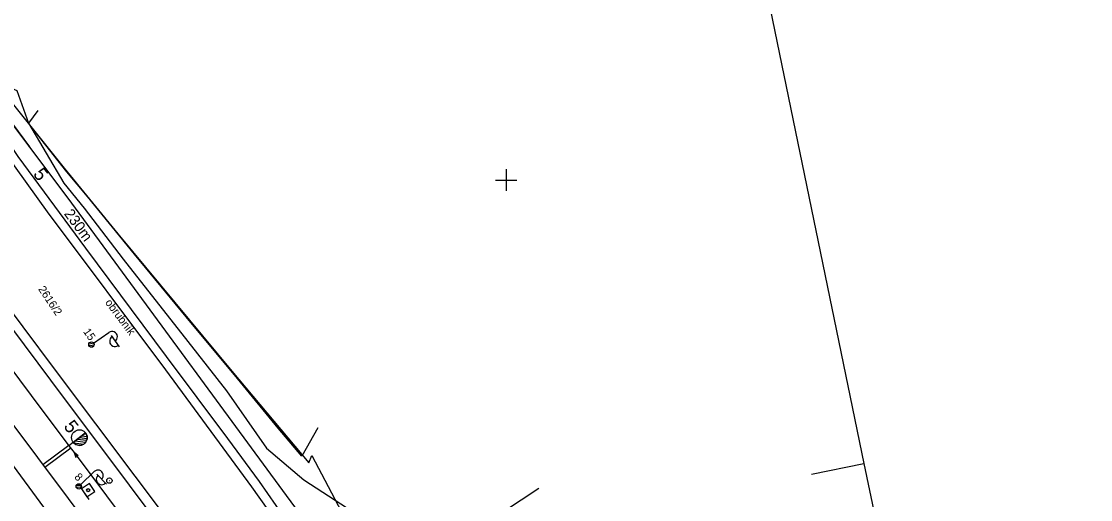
# Model space of a CAD drawing. Extents: x -804166 to -803706, y -1151030 to -1150147.
# Drawn here: x -803990.8 to -803790.5, y -1150359.8 to -1150270.3 of the extents above; entities that cross this region are included whole.
import ezdxf

# ---------------------------------------------------------------- set-up
doc = ezdxf.new("R2010")
doc.units = 0
for name, color, linetype in [('0381KM032-037P - Vrstva 1', 7, 'Continuous'), ('0381KM032-037P - Vrstva 17', 7, 'Continuous'), ('0381KM032-037P - Vrstva 2', 7, 'Continuous'), ('0381KM032-037P - Vrstva 25', 7, 'Continuous'), ('0381KM032-037P - Vrstva 27', 7, 'Continuous'), ('0381KM032-037P - Vrstva 3', 7, 'Continuous'), ('0381KM032-037P - Vrstva 4', 7, 'Continuous'), ('0381KM032-037P - Vrstva 49', 7, 'Continuous'), ('0381KM032-037P - Vrstva 51', 7, 'Continuous'), ('0381KM032-037P - Vrstva 57', 7, 'Continuous'), ('0381KM032-037P - Vrstva 7', 7, 'Continuous'), ('formát', 7, 'Continuous'), ('hran DP - hran DP', 7, 'Continuous'), ('krizky_1000 - Vrstva 1', 7, 'Continuous')]:
    doc.layers.add(name, color=color, linetype=linetype)

msp = doc.modelspace()

# ---------------------------------------------------------------- linework, layer by layer
at = {"layer": '0381KM032-037P - Vrstva 1'}
for points in [[(-804087.93, -1150205.28), (-804078.71, -1150215.28), (-804072.37, -1150222.52), (-804072.08, -1150222.85), (-804071.47, -1150223.58), (-804065.48, -1150230.82), (-804059.47, -1150238.51), (-804055.55, -1150243.68), (-804054.36, -1150245.27), (-804043.89, -1150259.22), (-804035.37, -1150270.61), (-804034.4, -1150271.93), (-804017.97, -1150293.92), (-804002.6, -1150314.46), (-803985.38, -1150337.43), (-803955.87, -1150376.72)], [(-804089.35, -1150206.44), (-804078.67, -1150220.7), (-804069.15, -1150233.38), (-804067.86, -1150235.11), (-804059.28, -1150246.53), (-804058.07, -1150248.16), (-804048.7, -1150260.65), (-804037.85, -1150275.13), (-804021.63, -1150296.76), (-804006.14, -1150317.34), (-803988.98, -1150340.29), (-803981.9, -1150349.73)], [(-804090.39, -1150214.38), (-804086.65, -1150219.55), (-804073.82, -1150237.11), (-804072.56, -1150238.83), (-804064.05, -1150250.31), (-804062.81, -1150251.97), (-804052.29, -1150266.05), (-804042.5, -1150279.11), (-804026.55, -1150300.33), (-804011.27, -1150320.63), (-803993.37, -1150344.49), (-803965.17, -1150382.07), (-803953.84, -1150397.19)], [(-804093.97, -1150217.42), (-804088.17, -1150225.67), (-804077.51, -1150240.28), (-804068.52, -1150252.21), (-804067.31, -1150253.81), (-804055.01, -1150270.12), (-804046.09, -1150281.93), (-804030.05, -1150303.21), (-804014.76, -1150323.52), (-803996.92, -1150347.35), (-803968.88, -1150385.42), (-803942.6, -1150419.03)], [(-804011.14, -1150262.39), (-804005.45, -1150273.41), (-803998.73, -1150284.85), (-803991.51, -1150295.63), (-803978.8, -1150312.77), (-803963.69, -1150332.99), (-803952.21, -1150348.36), (-803946.3, -1150356.39), (-803941.6, -1150363.14), (-803936.71, -1150370.83), (-803932.05, -1150378.84), (-803927.78, -1150386.91), (-803924.06, -1150395.18), (-803920.62, -1150403.65), (-803918.06, -1150410.86), (-803915.07, -1150420.32), (-803912.96, -1150427.25), (-803910.49, -1150435.34), (-803907.33, -1150445.05), (-803903.67, -1150454.38), (-803897.94, -1150464.6), (-803891.97, -1150476.6)], [(-803981.9, -1150349.73), (-803980.96, -1150350.97), (-803971.94, -1150363.03), (-803962.12, -1150376.15)], [(-803981.9, -1150349.73), (-803980.96, -1150350.97), (-803971.94, -1150363.03), (-803963.66, -1150377.12)]]:
    msp.add_lwpolyline(points, dxfattribs=at)
at = {"layer": '0381KM032-037P - Vrstva 17'}
for p, q in [((-803987.75, -1150286.99), (-803989.47, -1150289.34)), ((-803935.29, -1150346.34), (-803938.3, -1150351.66))]:
    msp.add_line(p, q, dxfattribs=at)
msp.add_lwpolyline([(-803938.3, -1150351.66), (-803942.72, -1150346.43), (-803950.36, -1150337.11), (-803959.95, -1150325.57), (-803969.63, -1150313.89), (-803978.45, -1150303.11), (-803982.31, -1150298.44), (-803989.47, -1150289.34)], dxfattribs=at)
at = {"layer": '0381KM032-037P - Vrstva 2'}
for p, q in [((-803981.09, -1150349.09), (-803978.8, -1150347.27)), ((-803978.8, -1150347.27), (-803981.09, -1150349.09)), ((-803979.09, -1150347.51), (-803978.62, -1150347.56)), ((-803981.1, -1150349.09), (-803981.9, -1150349.73)), ((-803981.09, -1150349.09), (-803981.09, -1150349.09)), ((-803981.02, -1150349.17), (-803979.13, -1150349.39)), ((-803980.76, -1150348.82), (-803978.78, -1150349.06)), ((-803980.35, -1150348.49), (-803978.58, -1150348.7)), ((-803979.93, -1150348.17), (-803978.49, -1150348.33)), ((-803979.51, -1150347.84), (-803978.5, -1150347.96))]:
    msp.add_line(p, q, dxfattribs=at)
for points in [[(-803981.9, -1150349.73), (-803980.96, -1150350.97), (-803971.94, -1150363.03), (-803962.12, -1150376.15)], [(-803980.18, -1150351.59), (-803980.96, -1150350.97), (-803980.59, -1150351.9)]]:
    msp.add_lwpolyline(points, dxfattribs=at)
msp.add_circle((-803979.94, -1150348.18), 1.46, dxfattribs=at)
msp.add_arc((-803979.95, -1150348.18), 1.46, 218.2901, 38.251, dxfattribs=at)
at = {"layer": '0381KM032-037P - Vrstva 25'}
for p, q in [((-803977.29, -1150330.5), (-803974.41, -1150328.51)), ((-803974.01, -1150329.08), (-803972.53, -1150331.22)), ((-803978.2, -1150330.83), (-803977.25, -1150331.01)), ((-803978.09, -1150330.47), (-803977.23, -1150330.63)), ((-803979.7, -1150356.96), (-803977.17, -1150354.55)), ((-803976.69, -1150355.05), (-803974.89, -1150356.93)), ((-803980.55, -1150357.43), (-803979.59, -1150357.46)), ((-803980.5, -1150357.06), (-803979.62, -1150357.08))]:
    msp.add_line(p, q, dxfattribs=at)
for centre in [(-803977.7, -1150330.78), (-803977.7, -1150330.78), (-803980.07, -1150357.31), (-803980.07, -1150357.31)]:
    msp.add_circle(centre, 0.5, dxfattribs=at)
for centre, start, end in [((-803973.84, -1150329.33), 304.6353, 124.6353), ((-803973.28, -1150330.16), 123.9327, 305.3379), ((-803976.48, -1150355.27), 313.6296, 133.6296), ((-803975.8, -1150356), 132.927, 314.3322)]:
    msp.add_arc(centre, 1, start, end, dxfattribs=at)
at = {"layer": '0381KM032-037P - Vrstva 27'}
msp.add_line((-803974.39, -1150356.24), (-803974.29, -1150356.24), dxfattribs=at)
msp.add_circle((-803974.34, -1150356.24), 0.5, dxfattribs=at)
at = {"layer": '0381KM032-037P - Vrstva 3'}
for p, q in [((-803979.88, -1150357.31), (-803978.21, -1150359.75)), ((-803978.08, -1150356.8), (-803979.54, -1150357.8)), ((-803977.08, -1150358.26), (-803978.08, -1150356.8)), ((-803948.98, -1150393.6), (-803893.86, -1150357.66)), ((-803979.54, -1150357.8), (-803978.54, -1150359.26)), ((-803978.54, -1150359.26), (-803977.08, -1150358.26))]:
    msp.add_line(p, q, dxfattribs=at)
msp.add_circle((-803978.31, -1150358.03), 0.296, dxfattribs=at)
at = {"layer": '0381KM032-037P - Vrstva 4'}
for points in [[(-804015.09, -1150257.7), (-804005.61, -1150276.65), (-803997.81, -1150289.61), (-803985.99, -1150305.97), (-803963.83, -1150335.54), (-803947.69, -1150357.39), (-803941.6, -1150366.02), (-803933.49, -1150379.54), (-803925.57, -1150395.83), (-803919.57, -1150411.36), (-803915.11, -1150425.7)], [(-804033.34, -1150270.47), (-804023.51, -1150283.74), (-804006.75, -1150306.05), (-804002.75, -1150311.23), (-803984.52, -1150335.59), (-803962.04, -1150365.45)]]:
    msp.add_lwpolyline(points, dxfattribs=at)
at = {"layer": '0381KM032-037P - Vrstva 49'}
for points in [[(-804010.87, -1150255.86), (-804001.61, -1150274.67), (-803994.7, -1150286.68), (-803981.46, -1150304.36), (-803936.05, -1150366.09), (-803921.77, -1150392.54), (-803912.22, -1150419.28), (-803908.81, -1150430.91)], [(-804010.87, -1150255.86), (-804010.87, -1150255.86), (-804001.65, -1150274.6), (-803994.86, -1150286.39), (-803989.31, -1150293.81), (-803989.41, -1150293.74)], [(-803998.25, -1150280.5), (-803991.69, -1150283.27), (-803989.47, -1150289.34)], [(-803989.47, -1150289.34), (-803982.88, -1150300.61), (-803979.03, -1150305.25), (-803971.78, -1150314.79), (-803959.62, -1150330.2), (-803952.37, -1150339.47), (-803944.88, -1150350.15), (-803937.92, -1150356.12), (-803929.73, -1150361.39)]]:
    msp.add_lwpolyline(points, dxfattribs=at)
at = {"layer": '0381KM032-037P - Vrstva 51'}
msp.add_lwpolyline([(-804015.09, -1150257.7), (-804005.61, -1150276.65), (-803997.81, -1150289.61), (-803985.99, -1150305.97), (-803963.83, -1150335.54), (-803947.69, -1150357.39), (-803941.6, -1150366.02), (-803933.49, -1150379.54), (-803925.57, -1150395.83), (-803919.57, -1150411.36), (-803915.11, -1150425.7)], dxfattribs=at)
at = {"layer": '0381KM032-037P - Vrstva 7'}
for p, q in [((-803981.94, -1150349.67), (-803986.77, -1150353.29)), ((-803981.58, -1150350.15), (-803986.41, -1150353.77))]:
    msp.add_line(p, q, dxfattribs=at)
at = {"layer": 'formát'}
for p, q in [((-803875.43, -1150147.35), (-803832.97, -1150353.01)), ((-803842.77, -1150355.03), (-803832.97, -1150353.01)), ((-803842.77, -1150355.03), (-803832.97, -1150353.01)), ((-803832.97, -1150353.01), (-803790.51, -1150558.67))]:
    msp.add_line(p, q, dxfattribs=at)
at = {"layer": 'hran DP - hran DP'}
for p, q in [((-803997.02, -1150280.06), (-803982.8, -1150297.76)), ((-803982.8, -1150297.76), (-803972.77, -1150310.06)), ((-803972.77, -1150310.06), (-803951.37, -1150335.75)), ((-803951.37, -1150335.75), (-803936.98, -1150352.88)), ((-803936.98, -1150352.88), (-803936.41, -1150351.52)), ((-803936.41, -1150351.52), (-803914.94, -1150392.05))]:
    msp.add_line(p, q, dxfattribs=at)
at = {"layer": 'krizky_1000 - Vrstva 1'}
for points in [[(-803900, -1150298), (-803900, -1150302)], [(-803902, -1150300), (-803898, -1150300)]]:
    msp.add_lwpolyline(points, dxfattribs=at)

# ---------------------------------------------------------------- texts
at = {"layer": '0381KM032-037P - Vrstva 1'}
for s, height, rotation, p in [('5', 2.5, 307.3088, (-803988.73, -1150298.92)), ('230m', 2, 306.5584, (-803982.92, -1150306.33))]:
    msp.add_text(s, height=height, rotation=rotation, dxfattribs=at).set_placement(p)
at = {"layer": '0381KM032-037P - Vrstva 2'}
msp.add_text('5', height=2.5, rotation=308.2705, dxfattribs=at).set_placement((-803983.01, -1150346.15))
at = {"layer": '0381KM032-037P - Vrstva 25'}
for s, rotation, p in [('15', 304.6353, (-803979.31, -1150328.36)), ('8', 313.6296, (-803981, -1150355.67))]:
    msp.add_text(s, height=1.5, rotation=rotation, dxfattribs=at).set_placement(p)
at = {"layer": '0381KM032-037P - Vrstva 51'}
msp.add_text('obrubník', height=1.5, rotation=306.842, dxfattribs=at).set_placement((-803975.21, -1150322.95))
at = {"layer": '0381KM032-037P - Vrstva 57'}
msp.add_text('2616/2', height=1.5, rotation=303.9651, dxfattribs=at).set_placement((-803987.73, -1150320.43))

doc.saveas('drawing.dxf')
